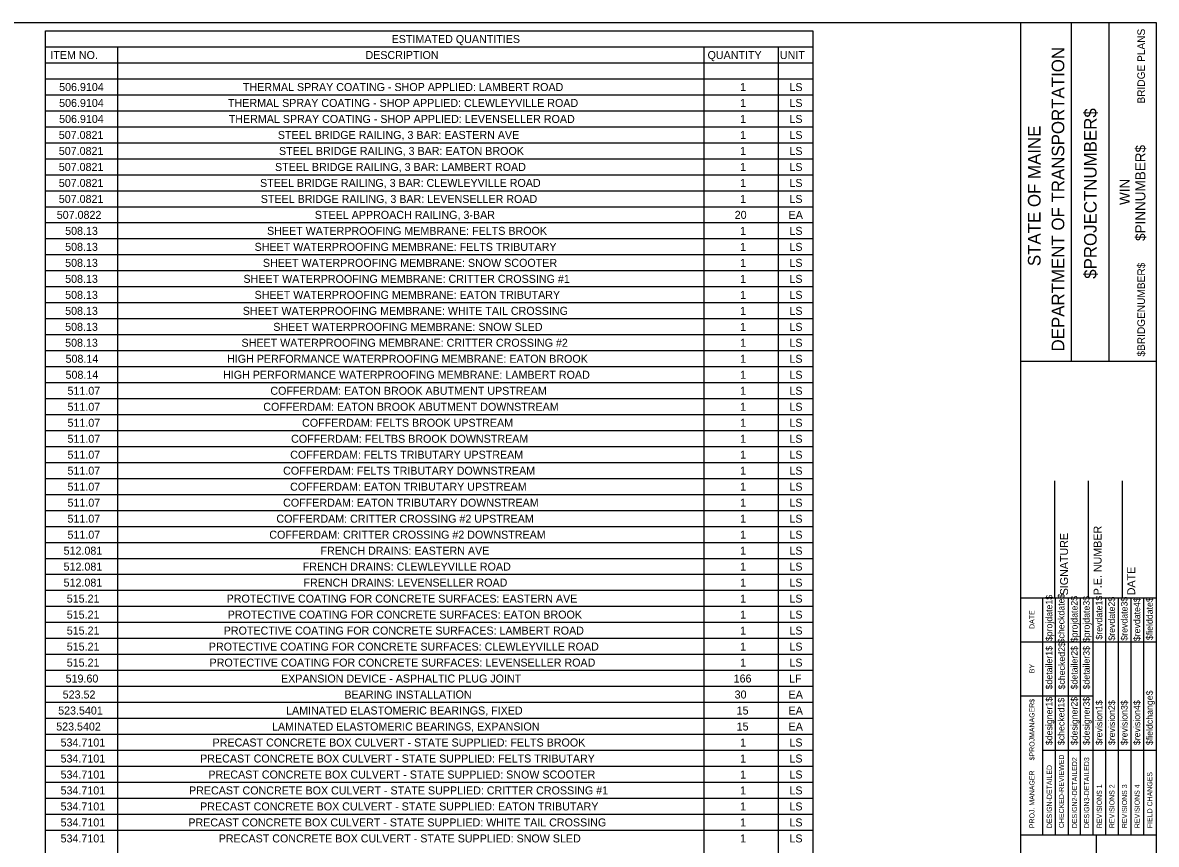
# Model space of a CAD drawing. Extents: x -18.7 to 5.6, y -2.7 to 4.
# Drawn here: x -8.508 to -7.113, y 2.973 to 3.985 of the extents above; entities that cross this region are included whole.
import ezdxf

# ---------------------------------------------------------------- set-up
doc = ezdxf.new("R2010")
doc.units = 0
for name, color, linetype in [('ANNOTATION', 7, 'Continuous'), ('BORDER', 7, 'Continuous'), ('BRIDGE_TITLE', 7, 'Continuous')]:
    doc.layers.add(name, color=color, linetype=linetype)

msp = doc.modelspace()

# ---------------------------------------------------------------- linework, layer by layer
at = {"layer": 'BORDER'}
for p, q in [((-7.2797, 2.2348), (-7.2797, 3.9848)), ((-7.2176, 3.5681), (-7.2176, 3.9847)), ((-7.171, 3.5681), (-7.171, 3.9847)), ((-8.4798, 3.9551), (-7.5355, 3.9551)), ((-8.3912, 3.9551), (-8.3912, 2.2424)), ((-7.6699, 3.9551), (-7.6699, 2.2424)), ((-7.5785, 3.9551), (-7.5785, 2.2424)), ((-8.4798, 3.9354), (-7.5355, 3.9354)), ((-8.4798, 3.9157), (-7.5355, 3.9157)), ((-8.4798, 3.896), (-7.5355, 3.896)), ((-8.4798, 3.8764), (-7.5355, 3.8764)), ((-8.4798, 3.8567), (-7.5355, 3.8567)), ((-8.4798, 3.837), (-7.5355, 3.837)), ((-8.4798, 3.8173), (-7.5355, 3.8173)), ((-8.4798, 3.7976), (-7.5355, 3.7976)), ((-8.4798, 3.7779), (-7.5355, 3.7779)), ((-8.4798, 3.7582), (-7.5355, 3.7582)), ((-8.4798, 3.7386), (-7.5355, 3.7386)), ((-8.4798, 3.7189), (-7.5355, 3.7189)), ((-8.4798, 3.6992), (-7.5355, 3.6992)), ((-8.4798, 3.6795), (-7.5355, 3.6795)), ((-8.4798, 3.6598), (-7.5355, 3.6598)), ((-8.4798, 3.6401), (-7.5355, 3.6401)), ((-8.4798, 3.6204), (-7.5355, 3.6204)), ((-8.4798, 3.6008), (-7.5355, 3.6008)), ((-8.4798, 3.5811), (-7.5355, 3.5811)), ((-8.4798, 3.5614), (-7.5355, 3.5614)), ((-7.2797, 3.568), (-7.1131, 3.568)), ((-8.4798, 3.5417), (-7.5355, 3.5417)), ((-8.4798, 3.522), (-7.5355, 3.522)), ((-8.4798, 3.5023), (-7.5355, 3.5023)), ((-8.4798, 3.4826), (-7.5355, 3.4826)), ((-8.4798, 3.463), (-7.5355, 3.463)), ((-8.4798, 3.4433), (-7.5355, 3.4433)), ((-8.4798, 3.4236), (-7.5355, 3.4236)), ((-7.2381, 3.2765), (-7.2381, 3.4206)), ((-7.1964, 3.2765), (-7.1964, 3.4206)), ((-7.1547, 3.2765), (-7.1547, 3.4206)), ((-8.4798, 3.4039), (-7.5355, 3.4039)), ((-8.4798, 3.3842), (-7.5355, 3.3842)), ((-8.4798, 3.3645), (-7.5355, 3.3645)), ((-8.4798, 3.3448), (-7.5355, 3.3448)), ((-8.4798, 3.3251), (-7.5355, 3.3251)), ((-8.4798, 3.3055), (-7.5355, 3.3055)), ((-8.4798, 3.2858), (-7.5355, 3.2858)), ((-8.4798, 3.2661), (-7.5355, 3.2661)), ((-7.2797, 3.2765), (-7.1131, 3.2765)), ((-8.4798, 3.2464), (-7.5355, 3.2464)), ((-8.4798, 3.2267), (-7.5355, 3.2267)), ((-8.4798, 3.207), (-7.5355, 3.207)), ((-8.4798, 3.1873), (-7.5355, 3.1873)), ((-8.4798, 3.1677), (-7.5355, 3.1677)), ((-8.4798, 3.148), (-7.5355, 3.148)), ((-8.4798, 3.1283), (-7.5355, 3.1283)), ((-8.4798, 3.1086), (-7.5355, 3.1086)), ((-8.4798, 3.0889), (-7.5355, 3.0889)), ((-8.4798, 3.0692), (-7.5355, 3.0692)), ((-8.4798, 3.0495), (-7.5355, 3.0495)), ((-8.4798, 3.0299), (-7.5355, 3.0299)), ((-8.4798, 3.0102), (-7.5355, 3.0102)), ((-8.4798, 2.9905), (-7.5355, 2.9905)), ((-7.2797, 2.9848), (-7.1131, 2.9848)), ((-7.1866, 2.4015), (-7.1866, 2.9848))]:
    msp.add_line(p, q, dxfattribs=at)
for points in [[(-9.7797, 3.9848), (-7.1131, 3.9848), (-7.1131, 2.2348), (-9.7797, 2.2348)], [(-8.4798, 3.9748), (-7.5355, 3.9748), (-7.5355, 2.2424), (-8.4798, 2.2424)]]:
    msp.add_lwpolyline(points, close=True, dxfattribs=at)
for points in [[(-7.2528, 3.2223), (-7.2528, 3.2765)], [(-7.2528, 2.9849), (-7.2528, 3.2647)], [(-7.2373, 2.9849), (-7.2373, 3.2765)], [(-7.2217, 3.2765), (-7.2217, 2.9849)], [(-7.2062, 2.9849), (-7.2062, 3.2765)], [(-7.1907, 2.9849), (-7.1907, 3.2765)], [(-7.1752, 2.9849), (-7.1752, 3.2765)], [(-7.1596, 2.9849), (-7.1596, 3.2765)], [(-7.1441, 2.9849), (-7.1441, 3.2765)], [(-7.1286, 2.9849), (-7.1286, 3.2765)], [(-7.2797, 3.2223), (-7.1131, 3.2223)], [(-7.2797, 3.1557), (-7.2528, 3.1557)], [(-7.2528, 3.1557), (-7.1907, 3.1557)], [(-7.2528, 3.089), (-7.1131, 3.089)]]:
    msp.add_lwpolyline(points, dxfattribs=at)

# ---------------------------------------------------------------- texts
at = {"layer": 'ANNOTATION'}
for s, height, p in [('506.9104', 0.00984, (-8.463, 3.9006)), ('THERMAL SPRAY COATING - SHOP APPLIED: LAMBERT ROAD', 0.009843, (-8.2369, 3.9006)), ('1', 0.00984, (-7.6252, 3.9006)), ('LS', 0.00984, (-7.5645, 3.9006)), ('506.9104', 0.00984, (-8.463, 3.881)), ('THERMAL SPRAY COATING - SHOP APPLIED: CLEWLEYVILLE ROAD', 0.009843, (-8.2552, 3.881)), ('1', 0.00984, (-7.6252, 3.881)), ('LS', 0.00984, (-7.5645, 3.881)), ('506.9104', 0.00984, (-8.463, 3.8613)), ('THERMAL SPRAY COATING - SHOP APPLIED: LEVENSELLER ROAD', 0.009843, (-8.2543, 3.8613)), ('1', 0.00984, (-7.6252, 3.8613)), ('LS', 0.00984, (-7.5645, 3.8613)), ('507.0821', 0.00984, (-8.4634, 3.8416)), ('STEEL BRIDGE RAILING, 3 BAR: EASTERN AVE', 0.009843, (-8.1939, 3.8416)), ('1', 0.00984, (-7.6252, 3.8416)), ('LS', 0.00984, (-7.5645, 3.8416)), ('507.0821', 0.00984, (-8.4634, 3.8219)), ('STEEL BRIDGE RAILING, 3 BAR: EATON BROOK', 0.009843, (-8.1925, 3.8219)), ('1', 0.00984, (-7.6252, 3.8219)), ('LS', 0.00984, (-7.5645, 3.8219)), ('507.0821', 0.00984, (-8.4634, 3.8022)), ('STEEL BRIDGE RAILING, 3 BAR: LAMBERT ROAD', 0.009843, (-8.1974, 3.8022)), ('1', 0.00984, (-7.6252, 3.8022)), ('LS', 0.00984, (-7.5645, 3.8022)), ('507.0821', 0.00984, (-8.4634, 3.7825)), ('STEEL BRIDGE RAILING, 3 BAR: CLEWLEYVILLE ROAD', 0.009843, (-8.2158, 3.7825)), ('1', 0.00984, (-7.6252, 3.7825)), ('LS', 0.00984, (-7.5645, 3.7825)), ('507.0821', 0.00984, (-8.4634, 3.7628)), ('STEEL BRIDGE RAILING, 3 BAR: LEVENSELLER ROAD', 0.009843, (-8.2149, 3.7628)), ('1', 0.00984, (-7.6252, 3.7628)), ('LS', 0.00984, (-7.5645, 3.7628)), ('507.0822', 0.00984, (-8.4659, 3.7432)), ('STEEL APPROACH RAILING, 3-BAR', 0.009843, (-8.1484, 3.7432)), ('20', 0.00984, (-7.6318, 3.7432)), ('EA', 0.00984, (-7.5655, 3.7432)), ('508.13', 0.00984, (-8.4556, 3.7235)), ('SHEET WATERPROOFING MEMBRANE: FELTS BROOK', 0.009843, (-8.2072, 3.7235)), ('1', 0.00984, (-7.6252, 3.7235)), ('LS', 0.00984, (-7.5645, 3.7235)), ('508.13', 0.00984, (-8.4556, 3.7038)), ('SHEET WATERPROOFING MEMBRANE: FELTS TRIBUTARY', 0.009843, (-8.2225, 3.7038)), ('1', 0.00984, (-7.6252, 3.7038)), ('LS', 0.00984, (-7.5645, 3.7038)), ('508.13', 0.00984, (-8.4556, 3.6841)), ('SHEET WATERPROOFING MEMBRANE: SNOW SCOOTER', 0.009843, (-8.2123, 3.6841)), ('1', 0.00984, (-7.6252, 3.6841)), ('LS', 0.00984, (-7.5645, 3.6841)), ('508.13', 0.00984, (-8.4556, 3.6644)), ('SHEET WATERPROOFING MEMBRANE: CRITTER CROSSING #1', 0.009843, (-8.2362, 3.6644)), ('1', 0.00984, (-7.6252, 3.6644)), ('LS', 0.00984, (-7.5645, 3.6644)), ('508.13', 0.00984, (-8.4556, 3.6447)), ('SHEET WATERPROOFING MEMBRANE: EATON TRIBUTARY', 0.009843, (-8.2225, 3.6447)), ('1', 0.00984, (-7.6252, 3.6447)), ('LS', 0.00984, (-7.5645, 3.6447)), ('508.13', 0.00984, (-8.4556, 3.625)), ('SHEET WATERPROOFING MEMBRANE: WHITE TAIL CROSSING', 0.009843, (-8.237, 3.625)), ('1', 0.00984, (-7.6252, 3.625)), ('LS', 0.00984, (-7.5645, 3.625)), ('508.13', 0.00984, (-8.4556, 3.6053)), ('SHEET WATERPROOFING MEMBRANE: SNOW SLED', 0.009843, (-8.1995, 3.6053)), ('1', 0.00984, (-7.6252, 3.6053)), ('LS', 0.00984, (-7.5645, 3.6053)), ('508.13', 0.00984, (-8.4556, 3.5857)), ('SHEET WATERPROOFING MEMBRANE: CRITTER CROSSING #2', 0.009843, (-8.2386, 3.5857)), ('1', 0.00984, (-7.6252, 3.5857)), ('LS', 0.00984, (-7.5645, 3.5857)), ('508.14', 0.00984, (-8.4551, 3.566)), ('HIGH PERFORMANCE WATERPROOFING MEMBRANE: EATON BROOK', 0.009843, (-8.2564, 3.566)), ('1', 0.00984, (-7.6252, 3.566)), ('LS', 0.00984, (-7.5645, 3.566)), ('508.14', 0.00984, (-8.4551, 3.5463)), ('HIGH PERFORMANCE WATERPROOFING MEMBRANE: LAMBERT ROAD', 0.009843, (-8.2613, 3.5463)), ('1', 0.00984, (-7.6252, 3.5463)), ('LS', 0.00984, (-7.5645, 3.5463)), ('511.07', 0.00984, (-8.4527, 3.5266)), ('COFFERDAM: EATON BROOK ABUTMENT UPSTREAM', 0.009843, (-8.2031, 3.5266)), ('1', 0.00984, (-7.6252, 3.5266)), ('LS', 0.00984, (-7.5645, 3.5266)), ('511.07', 0.00984, (-8.4527, 3.5069)), ('COFFERDAM: EATON BROOK ABUTMENT DOWNSTREAM', 0.009843, (-8.2118, 3.5069)), ('1', 0.00984, (-7.6252, 3.5069)), ('LS', 0.00984, (-7.5645, 3.5069)), ('511.07', 0.00984, (-8.4527, 3.4872)), ('COFFERDAM: FELTS BROOK UPSTREAM', 0.009843, (-8.1641, 3.4872)), ('1', 0.00984, (-7.6252, 3.4872)), ('LS', 0.00984, (-7.5645, 3.4872)), ('511.07', 0.00984, (-8.4527, 3.4675)), ('COFFERDAM: FELTBS BROOK DOWNSTREAM', 0.009843, (-8.1776, 3.4675)), ('1', 0.00984, (-7.6252, 3.4675)), ('LS', 0.00984, (-7.5645, 3.4675)), ('511.07', 0.00984, (-8.4527, 3.4479)), ('COFFERDAM: FELTS TRIBUTARY UPSTREAM', 0.009843, (-8.1787, 3.4479)), ('1', 0.00984, (-7.6252, 3.4479)), ('LS', 0.00984, (-7.5645, 3.4479)), ('511.07', 0.00984, (-8.4527, 3.4282)), ('COFFERDAM: FELTS TRIBUTARY DOWNSTREAM', 0.009843, (-8.1874, 3.4282)), ('1', 0.00984, (-7.6252, 3.4282)), ('LS', 0.00984, (-7.5645, 3.4282)), ('511.07', 0.00984, (-8.4527, 3.4085)), ('COFFERDAM: EATON TRIBUTARY UPSTREAM', 0.009843, (-8.1788, 3.4085)), ('1', 0.00984, (-7.6252, 3.4085)), ('LS', 0.00984, (-7.5645, 3.4085)), ('511.07', 0.00984, (-8.4527, 3.3888)), ('COFFERDAM: EATON TRIBUTARY DOWNSTREAM', 0.009843, (-8.1874, 3.3888)), ('1', 0.00984, (-7.6252, 3.3888)), ('LS', 0.00984, (-7.5645, 3.3888)), ('511.07', 0.00984, (-8.4527, 3.3691)), ('COFFERDAM: CRITTER CROSSING #2 UPSTREAM', 0.009843, (-8.1957, 3.3691)), ('1', 0.00984, (-7.6252, 3.3691)), ('LS', 0.00984, (-7.5645, 3.3691)), ('511.07', 0.00984, (-8.4527, 3.3494)), ('COFFERDAM: CRITTER CROSSING #2 DOWNSTREAM', 0.009843, (-8.2044, 3.3494)), ('1', 0.00984, (-7.6252, 3.3494)), ('LS', 0.00984, (-7.5645, 3.3494)), ('512.081', 0.00984, (-8.4575, 3.3297)), ('FRENCH DRAINS: EASTERN AVE', 0.009843, (-8.1414, 3.3297)), ('1', 0.00984, (-7.6252, 3.3297)), ('LS', 0.00984, (-7.5645, 3.3297)), ('512.081', 0.00984, (-8.4575, 3.3101)), ('FRENCH DRAINS: CLEWLEYVILLE ROAD', 0.009843, (-8.1633, 3.3101)), ('1', 0.00984, (-7.6252, 3.3101)), ('LS', 0.00984, (-7.5645, 3.3101)), ('512.081', 0.00984, (-8.4575, 3.2904)), ('FRENCH DRAINS: LEVENSELLER ROAD', 0.009843, (-8.1624, 3.2904)), ('1', 0.00984, (-7.6252, 3.2904)), ('LS', 0.00984, (-7.5645, 3.2904)), ('515.21', 0.00984, (-8.4536, 3.2707)), ('PROTECTIVE COATING FOR CONCRETE SURFACES: EASTERN AVE', 0.009843, (-8.2569, 3.2707)), ('1', 0.00984, (-7.6252, 3.2707)), ('LS', 0.00984, (-7.5645, 3.2707)), ('515.21', 0.00984, (-8.4536, 3.251)), ('PROTECTIVE COATING FOR CONCRETE SURFACES: EATON BROOK', 0.009843, (-8.2556, 3.251)), ('1', 0.00984, (-7.6252, 3.251)), ('LS', 0.00984, (-7.5645, 3.251)), ('515.21', 0.00984, (-8.4536, 3.2313)), ('PROTECTIVE COATING FOR CONCRETE SURFACES: LAMBERT ROAD', 0.009843, (-8.2605, 3.2313)), ('1', 0.00984, (-7.6252, 3.2313)), ('LS', 0.00984, (-7.5645, 3.2313)), ('515.21', 0.00984, (-8.4536, 3.2116)), ('PROTECTIVE COATING FOR CONCRETE SURFACES: CLEWLEYVILLE ROAD', 0.009843, (-8.2788, 3.2116)), ('1', 0.00984, (-7.6252, 3.2116)), ('LS', 0.00984, (-7.5645, 3.2116)), ('515.21', 0.00984, (-8.4536, 3.1919)), ('PROTECTIVE COATING FOR CONCRETE SURFACES: LEVENSELLER ROAD', 0.009843, (-8.2779, 3.1919)), ('1', 0.00984, (-7.6252, 3.1919)), ('LS', 0.00984, (-7.5645, 3.1919)), ('519.60', 0.00984, (-8.455, 3.1723)), ('EXPANSION DEVICE - ASPHALTIC PLUG JOINT', 0.009843, (-8.19, 3.1723)), ('166', 0.00984, (-7.6331, 3.1723)), ('LF', 0.00984, (-7.5649, 3.1723)), ('523.52', 0.00984, (-8.4586, 3.1526)), ('BEARING INSTALLATION', 0.009843, (-8.112, 3.1526)), ('30', 0.00984, (-7.6319, 3.1526)), ('EA', 0.00984, (-7.5655, 3.1526)), ('523.5401', 0.00984, (-8.4642, 3.1329)), ('LAMINATED ELASTOMERIC BEARINGS, FIXED', 0.009843, (-8.1838, 3.1329)), ('15', 0.00984, (-7.6294, 3.1329)), ('EA', 0.00984, (-7.5655, 3.1329)), ('523.5402', 0.00984, (-8.4666, 3.1132)), ('LAMINATED ELASTOMERIC BEARINGS, EXPANSION', 0.009843, (-8.2011, 3.1132)), ('15', 0.00984, (-7.6294, 3.1132)), ('EA', 0.00984, (-7.5655, 3.1132)), ('534.7101', 0.00984, (-8.4612, 3.0935)), ('PRECAST CONCRETE BOX CULVERT - STATE SUPPLIED: FELTS BROOK', 0.009843, (-8.2742, 3.0935)), ('1', 0.00984, (-7.6252, 3.0935)), ('LS', 0.00984, (-7.5645, 3.0935)), ('534.7101', 0.00984, (-8.4612, 3.0738)), ('PRECAST CONCRETE BOX CULVERT - STATE SUPPLIED: FELTS TRIBUTARY', 0.009843, (-8.2895, 3.0738)), ('1', 0.00984, (-7.6252, 3.0738)), ('LS', 0.00984, (-7.5645, 3.0738)), ('534.7101', 0.00984, (-8.4612, 3.0541)), ('PRECAST CONCRETE BOX CULVERT - STATE SUPPLIED: SNOW SCOOTER', 0.009843, (-8.2794, 3.0541)), ('1', 0.00984, (-7.6252, 3.0541)), ('LS', 0.00984, (-7.5645, 3.0541)), ('534.7101', 0.00984, (-8.4612, 3.0345)), ('PRECAST CONCRETE BOX CULVERT - STATE SUPPLIED: CRITTER CROSSING #1', 0.009843, (-8.3032, 3.0345)), ('1', 0.00984, (-7.6252, 3.0345)), ('LS', 0.00984, (-7.5645, 3.0345)), ('534.7101', 0.00984, (-8.4612, 3.0148)), ('PRECAST CONCRETE BOX CULVERT - STATE SUPPLIED: EATON TRIBUTARY', 0.009843, (-8.2895, 3.0148)), ('1', 0.00984, (-7.6252, 3.0148)), ('LS', 0.00984, (-7.5645, 3.0148)), ('534.7101', 0.00984, (-8.4612, 2.9951)), ('PRECAST CONCRETE BOX CULVERT - STATE SUPPLIED: WHITE TAIL CROSSING', 0.009843, (-8.304, 2.9951)), ('1', 0.00984, (-7.6252, 2.9951)), ('LS', 0.00984, (-7.5645, 2.9951)), ('534.7101', 0.00984, (-8.4612, 2.9754)), ('PRECAST CONCRETE BOX CULVERT - STATE SUPPLIED: SNOW SLED', 0.009843, (-8.2666, 2.9754)), ('1', 0.00984, (-7.6252, 2.9754)), ('LS', 0.00984, (-7.5645, 2.9754))]:
    msp.add_text(s, height=height, dxfattribs=at).set_placement(p)
at = {"layer": 'BORDER'}
for s, height, p in [('ESTIMATED QUANTITIES', 0.009843, (-8.0539, 3.9597)), ('ITEM NO.', 0.00984, (-8.4738, 3.94)), ('DESCRIPTION', 0.009843, (-8.0861, 3.94)), ('QUANTITY', 0.00984, (-7.6652, 3.94)), ('UNIT', 0.00984, (-7.5762, 3.94))]:
    msp.add_text(s, height=height, dxfattribs=at).set_placement(p)
for s, height, p in [('DEPARTMENT OF TRANSPORTATION', 0.015529, (-7.2263, 3.5799)), ('$PROJECTNUMBER$', 0.015529, (-7.1865, 3.6694)), ('STATE OF MAINE', 0.015529, (-7.2555, 3.685)), ('$PINNUMBER$', 0.012421, (-7.1265, 3.716)), ('WIN', 0.01242, (-7.1458, 3.7603)), ('P.E. NUMBER', 0.009843, (-7.1804, 3.2797)), ('SIGNATURE', 0.00984, (-7.2217, 3.2797)), ('DATE', 0.00984, (-7.1391, 3.2797)), ('$projdate1$', 0.008076, (-7.241, 3.2232)), ('$checkdate$', 0.008076, (-7.2261, 3.2205)), ('$projdate2$', 0.008076, (-7.21, 3.2219)), ('$projdate3$', 0.008076, (-7.1951, 3.2219)), ('$revdate1$', 0.00808, (-7.1795, 3.2251)), ('$revdate2$', 0.00808, (-7.164, 3.2238)), ('$revdate3$', 0.00808, (-7.1485, 3.2238)), ('$revdate4$', 0.00808, (-7.1329, 3.2232)), ('$fielddate$', 0.008076, (-7.1174, 3.2245)), ('DATE', 0.00619, (-7.263, 3.2383)), ('$detailer1$', 0.008076, (-7.241, 3.1638)), ('$checked2$', 0.00808, (-7.2255, 3.1638)), ('$detailer2$', 0.008076, (-7.21, 3.1638)), ('$detailer3$', 0.008076, (-7.1951, 3.1638)), ('BY', 0.00619, (-7.263, 3.1838)), ('$designer1$', 0.008076, (-7.241, 3.0952)), ('$checked1$', 0.00808, (-7.2261, 3.0952)), ('$designer2$', 0.008076, (-7.21, 3.0952)), ('$designer3$', 0.008076, (-7.1951, 3.0952)), ('$fieldchange$', 0.008076, (-7.1174, 3.0952)), ('$PROJMANAGER$', 0.006212, (-7.263, 3.0764)), ('$revision1$', 0.008076, (-7.1795, 3.0952)), ('$revision2$', 0.008076, (-7.164, 3.0952)), ('$revision3$', 0.008076, (-7.1485, 3.0952)), ('$revision4$', 0.008076, (-7.1329, 3.0952)), ('CHECKED-REVIEWED', 0.006212, (-7.2267, 2.993)), ('DESIGN2-DETAILED2', 0.006212, (-7.2106, 2.993)), ('DESIGN3-DETAILED3', 0.006212, (-7.1957, 2.993)), ('PROJ. MANAGER', 0.006212, (-7.263, 2.993)), ('DESIGN-DETAILED', 0.006212, (-7.2416, 2.993)), ('FIELD CHANGES', 0.006212, (-7.118, 2.993)), ('REVISIONS 1', 0.006212, (-7.1801, 2.993)), ('REVISIONS 2', 0.006212, (-7.1646, 2.993)), ('REVISIONS 3', 0.006212, (-7.1491, 2.993)), ('REVISIONS 4', 0.006212, (-7.1336, 2.993))]:
    msp.add_text(s, height=height, rotation=90, dxfattribs=at).set_placement(p)
at = {"layer": 'BRIDGE_TITLE'}
for s, p in [('BRIDGE PLANS', (-7.1271, 3.8852)), ('$BRIDGENUMBER$', (-7.1271, 3.5736))]:
    msp.add_text(s, height=0.009317, rotation=90, dxfattribs=at).set_placement(p)

doc.saveas('drawing.dxf')
